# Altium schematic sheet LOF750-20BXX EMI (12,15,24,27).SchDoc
size A4; Revision: A; SheetNumber: 1; SheetTotal: 1
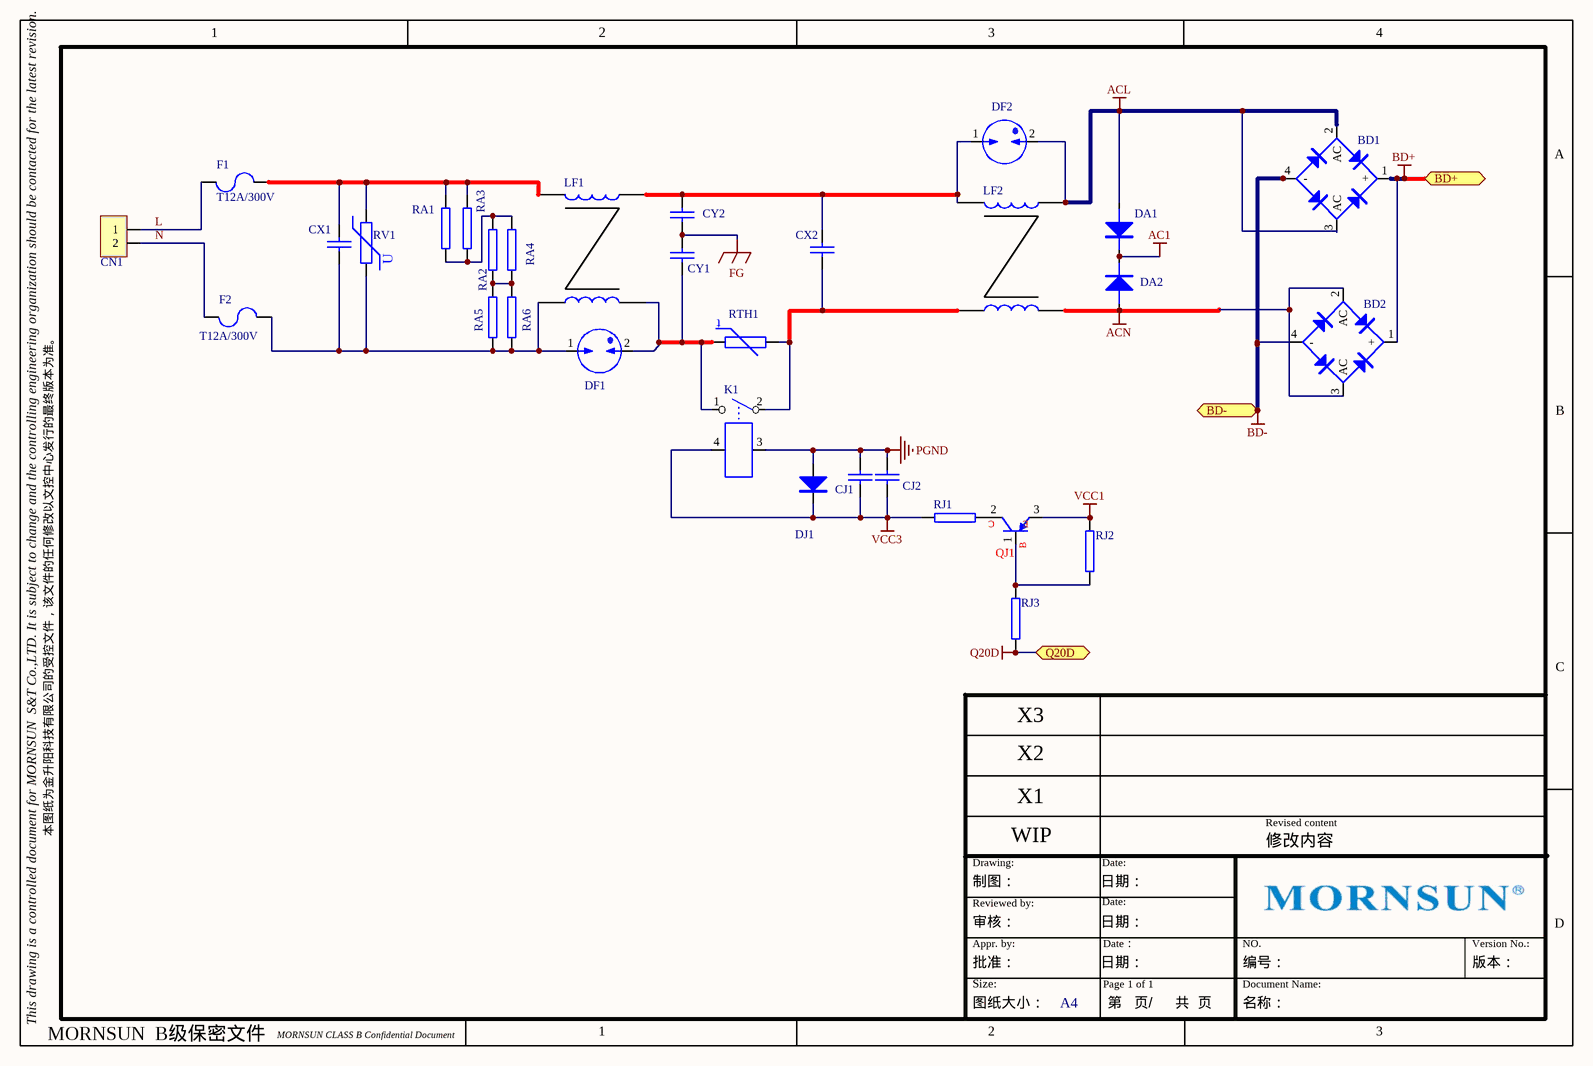
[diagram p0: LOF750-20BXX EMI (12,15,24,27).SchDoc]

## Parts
BD1  Bridge  [RTF-GBUXX-S]  (value not drawn)
BD2  Bridge  [RTF-GBUXX-S]  (value not drawn)
CJ1  y1 2n2  [SC-1206]  (value not drawn)
CJ2  y1 2n2  [SC-1206]  (value not drawn)
CN1  MHDR1X2  [CON-VH3.96-3A]  (value not drawn)
CX1  0.47U/275VAC/18*9*12.5  [CAP-15-18.0X10.0-X]  (value not drawn)
CX2  0.68U/275VAC/26*7*16  [CAP-15-18.0X7.0-X]  (value not drawn)
CY1  y1 2n2  [CAP-9.5-9.5X7.0-Y]  (value not drawn)
CY2  y1 2n2  [CAP-9.5-9.5X7.0-Y]  (value not drawn)
DA1  1N4007/SOD-123FL  [SOD-123&SD-1206]  (value not drawn)
DA2  1N4007/SOD-123FL  [SOD-123&SD-1206]  (value not drawn)
DF1  GDT2  [SD-3225]  (value not drawn)
DF2  GDT2  [SD-3225]  (value not drawn)
DJ1  SOD123  [SOD-123&SD-1206]  (value not drawn)
F1  T12A/300V  [FUSE-5.08-8.35X4.3-R]
F2  T12A/300V  [FUSE-5.08-8.35X4.3-R]
K1  36040016  [RLY-HF46F-G(H1)]  (value not drawn)
LF1  T18*10*6  D=0.8  [750W-LF1]  (value not drawn)
LF2  T22*18*8  线径D=0.85  [750W-LF2]  (value not drawn)
QJ1  SOT 89  [SOT-23A]  (value not drawn)
RA1  1.5M/1206  [SR-1206]  (value not drawn)
RA2  1.5M/1206  [SR-1206]  (value not drawn)
RA3  1.5M/1206  [SR-1206]  (value not drawn)
RA4  1.5M/1206  [SR-1206]  (value not drawn)
RA5  1.5M/1206  [SR-1206]  (value not drawn)
RA6  1.5M/1206  [SR-1206]  (value not drawn)
RJ1  100R/1206  [SR-1206]  (value not drawn)
RJ2  10K /0603  [SR-0603]  (value not drawn)
RJ3  10K /0805  [SR-0805]  (value not drawn)
RTH1  SCK 056  [TSR-7.5-10.0X5.5]  (value not drawn)
RV1  TVR10471M  [VSR-7.5-11.5X5.3]  (value not drawn)

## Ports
BD+ (bidir), BD- (bidir), Q20D (bidir)

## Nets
AC1: DA1.2(K) DA2.2(K)
ACL: BD1.2(AC) BD1.3(AC) DA1.1(A) DF2.2 LF2.1
ACN: BD1.4(-) BD2.2(AC) BD2.3(AC) BD2.4(-) DA2.1(A) LF2.2 ; port BD-  [also labelled BD-]
BD+: BD1.1(+) BD2.1(+) ; port BD+
FG: CY1.1 CY2.1
PGND: CJ1.2 CJ2.2 DJ1.1(A) K1.3
Q20D: RJ3.1 ; port Q20D
VCC1: QJ1.3(E) RJ2.2
VCC3: CJ1.1 CJ2.1 DJ1.2(K) K1.4 RJ1.2
L: CN1.1 F1.2
N: CN1.2 F2.2
NetCX1_1: CX1.1 F1.1 LF1.3 RA1.1 RA2.2 RV1.2
NetCX1_2: CX1.2 DF1.1 F2.1 LF1.4 RA5.1 RA6.1 RV1.1
NetCX2_1: CX2.1 CY2.2 DF2.1 LF1.2 LF2.4
NetCX2_2: CX2.2 K1.2 LF2.3 RTH1.2
NetCY1_2: CY1.2 DF1.2 K1.1 LF1.1 RTH1.1
NetQJ1_1: QJ1.1(B) RJ2.1 RJ3.2
NetQJ1_2: QJ1.2(C) RJ1.1
NetRA1_2: RA1.2 RA2.1 RA3.2 RA4.2
NetRA3_1: RA3.1 RA4.1 RA5.2 RA6.2

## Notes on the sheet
- 1
- 2
- 3
- 4
- A
- B
- X3
- C
- X2
- 本图纸为金升阳科技有限公司的受控文件，该文件的任何修改以文控中心发行的最终版本为准。
- Drawing:
- WIP
- X1
- Date:
- 修改内容
- Revised content
- Reviewed by:
- 审核：
- 制图：
- 日期：
- D
- Appr. by:
- Size:
- 批准：
- Page 1 of 1
- Date：
- Document Name:
- NO.
- 编号：
- Version No.:
- 版本：
- This drawing is a controlled document for MORNSUN  S&T Co.,LTD. It is subject to change and the controlling engineering organization should be contacted for the latest revision.
- MORNSUN  B级保密文件
- MORNSUN CLASS B Confidential Document
- 图纸大小：
- A4
- 第   页/
- 共  页
- 名称：

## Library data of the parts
CJ1 CJ2 CY1 CY2 = CAP: MPN: YU1AH222M090BAMD0H; PN: 30040010; APN: ??
CN1 = Pin2
CX1 CX2 = CAP: X2/474K/275VAC/18*18*9/PP; PN: 30040034
DA1 DA2 = DIODE: MPN: SK110; PN: 31000046
DJ1 = DI-1: MPN: BYD167ZH; PN: 31005002
F1 F2 = FUSE2: 6.3A/250V; Mfr: Dongguan Better; MPN: 932:4-6.3A/250V
K1 = RELAY(ALD112)
LF1 LF2 = NF: PN: 52105173; APN: ??
QJ1 = PNP: PNP Transistor
RA1-RA6 = RES1: PN: 35010052
RJ1 = RES1: PN: 35000056
RJ2 RJ3 = RES1: 2.2MΩ 1/8W ±1% 0805
RTH1 = RT
RV1 = RV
